
// ===== library types =====

// folder: SIKO GmbH

TYPE "DC_Com"
VERSION : 0.1
   STRUCT
      bc00 : Bool;
      bc01 : Bool;
      bc02 : Bool;
      bc03 : Bool;
      bc04 : Bool;
      bc05 : Bool;
      bc06 : Bool;
      bc07 : Bool;
      bc08 : Bool;
      bc09 : Bool;
      bc10 : Bool;
      bc11 : Bool;
      bc12 : Bool;
      bc13 : Bool;
      bc14 : Bool;
      bc15 : Bool;
      bcCal : Bool;
      bs00 : Bool;
      bs01 : Bool;
      bs02 : Bool;
      bs03 : Bool;
      bs04 : Bool;
      bs06 : Bool;
      bs07 : Bool;
      bs08 : Bool;
      bs09 : Bool;
      bs10 : Bool;
      bs11 : Bool;
      bs12 : Bool;
      bs13 : Bool;
      bs14 : Bool;
      bs15 : Bool;
      bsCalExec : Bool;
      nPara1Adr : Byte := BYTE#16#FE;
      nPara2Adr : Byte := BYTE#16#FE;
      nPara3Adr : Byte := BYTE#16#FE;
      nPara3Cmd : Byte;
      nPara3Val : DInt;
      bPara3Write : Bool;
      nPara1AdrRec : Byte;
      nPara1ValRec : DInt;
      nPara2AdrRec : Byte;
      nPara2ValRec : DInt;
      nPara3AdrRec : Byte;
      nPara3ValRec : DInt;
      bPara1FD : Bool;
      bPara2FD : Bool;
      bPara3FD : Bool;
      bsFaultDataRec : Bool;
      nErrCode1 : Byte;
      nErrCode2 : Byte;
      bs05 : Bool;
   END_STRUCT;
END_TYPE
